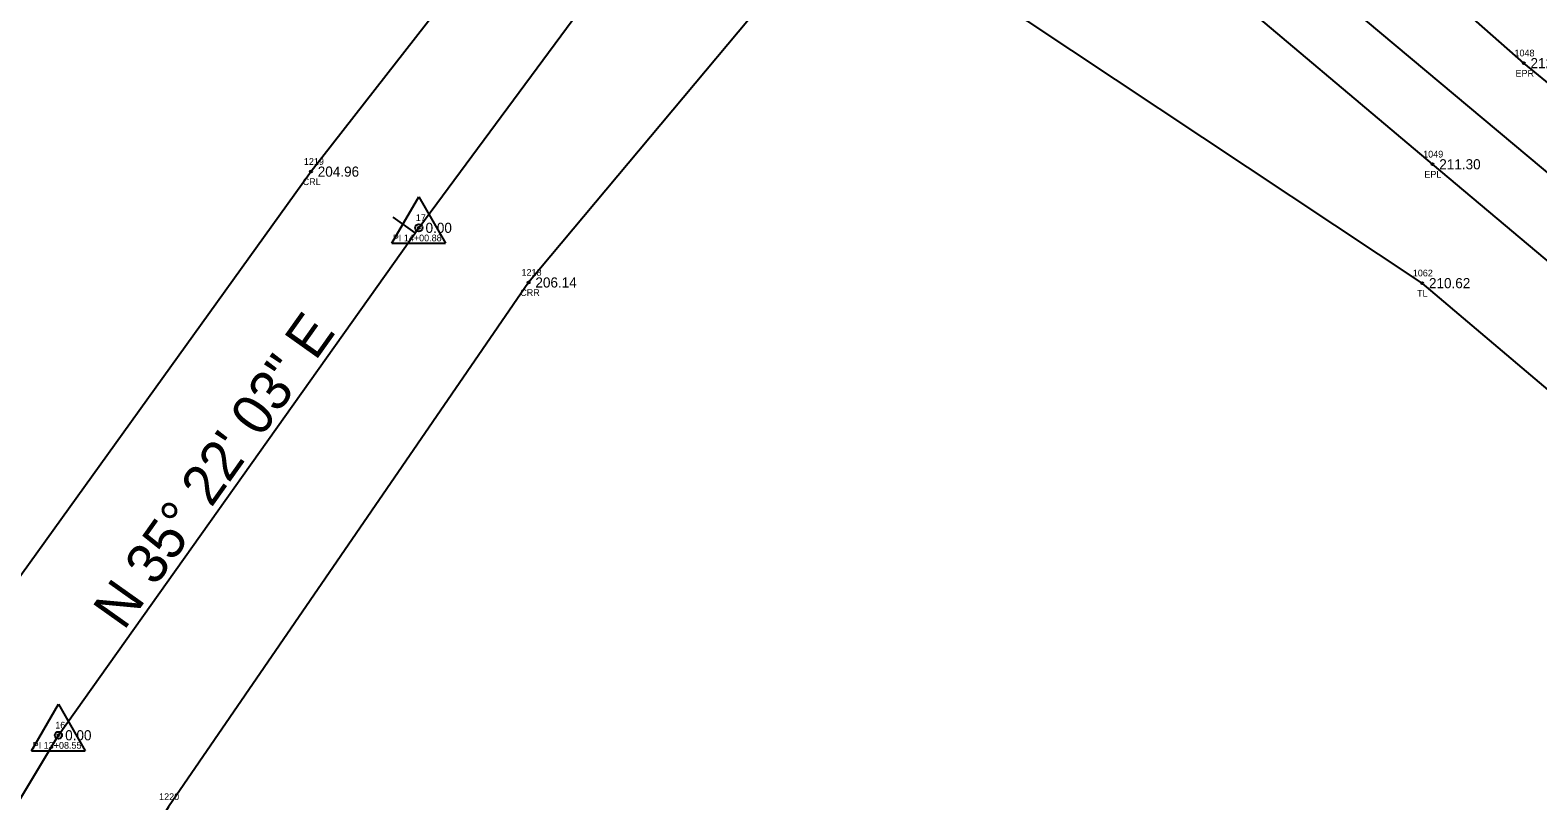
# Model space of a CAD drawing. Extents: x 2259948 to 2261336, y 1064647 to 1065986.
# Drawn here: x 2260676.5 to 2260900.1, y 1064908.1 to 1065022.5 of the extents above; entities that cross this region are included whole.
import ezdxf

# ---------------------------------------------------------------- set-up
doc = ezdxf.new("R2010")
doc.units = 0
for name, color, linetype in [('RD_EX_H2O', 7, 'Continuous'), ('RD_EX_H2O_txCode', 7, 'Continuous'), ('RD_EX_Road', 7, 'Continuous'), ('RD_EX_Road_txCode', 7, 'Continuous'), ('RD_EX_TX_H2O_ELEV', 7, 'Continuous'), ('RD_EX_TX_Road_ELEV', 7, 'Continuous'), ('RD_EX_TX_VEG_ELEV', 7, 'Continuous'), ('RD_EX_VEG', 7, 'Continuous'), ('RD_EX_VEG_txCode', 7, 'Continuous'), ('RD_HC_Cl', 7, 'Continuous'), ('RD_HC_Data', 7, 'Continuous'), ('RD_HC_Data_Tic', 7, 'Continuous'), ('RD_HC_Survey_ELEV', 7, 'Continuous'), ('RD_HC_txCode', 7, 'Continuous'), ('RD_SMD_Locator', 7, 'Continuous')]:
    doc.layers.add(name, color=color, linetype=linetype)

msp = doc.modelspace()

# ---------------------------------------------------------------- linework, layer by layer
at = {"layer": 'RD_EX_H2O'}
for points in [[(2260766.96, 1065089.79), (2260769.94, 1065084.22), (2260769.59, 1065075.21), (2260766.59, 1065063.56), (2260718.2, 1065001.51), (2260666.03, 1064928.94), (2260617.31, 1064851.47), (2260573.34, 1064761.94), (2260536.11, 1064718.88), (2260488.15, 1064682.39)], [(2260814.11, 1065053.05), (2260812.59, 1065051.01), (2260806.25, 1065051.8), (2260750.48, 1064985.06), (2260697.06, 1064907.27), (2260648.8, 1064826.07), (2260606.38, 1064743.85), (2260584.89, 1064714.82), (2260586.34, 1064702.25), (2260547.45, 1064661.75), (2260541.67, 1064664.24), (2260523.34, 1064649.3)]]:
    msp.add_lwpolyline(points, dxfattribs=at)
at = {"layer": 'RD_EX_Road'}
for points in [[(2261124.91, 1064827.37), (2261072.16, 1064871.6), (2261053.72, 1064886.47), (2261045.58, 1064893.1), (2260972.89, 1064954.76), (2260940.74, 1064982.39), (2260933.33, 1064988.76), (2260898.06, 1065017.6), (2260832.89, 1065075.07)], [(2261112.68, 1064810.86), (2261032.95, 1064877.72), (2260956.01, 1064942.53), (2260884.53, 1065002.6), (2260818.6, 1065058.26)]]:
    msp.add_lwpolyline(points, dxfattribs=at)
at = {"layer": 'RD_EX_VEG'}
msp.add_lwpolyline([(2261105.29, 1064796.67), (2260883, 1064984.96), (2260766.14, 1065062.68), (2260367.33, 1065416.28), (2260257.33, 1065527.76)], dxfattribs=at)
at = {"layer": 'RD_HC_Cl'}
for p, q in [((2261118.79, 1064819.11), (2260589.55, 1065263.13)), ((2260734.19, 1064993.17), (2260819.36, 1065108.41)), ((2260680.74, 1064917.88), (2260734.19, 1064993.17)), ((2260632.73, 1064838.31), (2260680.74, 1064917.88))]:
    msp.add_line(p, q, dxfattribs=at)
at = {"layer": 'RD_HC_Data'}
for p, q in [((2260730.21, 1064990.88), (2260734.19, 1064997.76)), ((2260734.19, 1064997.76), (2260738.16, 1064990.88)), ((2260730.21, 1064990.88), (2260738.16, 1064990.88)), ((2260676.77, 1064915.59), (2260680.74, 1064922.47)), ((2260680.74, 1064922.47), (2260684.71, 1064915.59)), ((2260676.77, 1064915.59), (2260684.71, 1064915.59))]:
    msp.add_line(p, q, dxfattribs=at)
for centre in [(2260734.19, 1064993.17), (2260680.74, 1064917.88)]:
    msp.add_circle(centre, 0.529, dxfattribs=at)
at = {"layer": 'RD_HC_Data_Tic'}
msp.add_line((2260733.67, 1064992.45), (2260730.41, 1064994.77), dxfattribs=at)
at = {"layer": 'RD_SMD_Locator'}
for centre in [(2260898.06, 1065017.6), (2260718.2, 1065001.51), (2260884.53, 1065002.6), (2260734.19, 1064993.17), (2260750.48, 1064985.06), (2260883, 1064984.96), (2260680.74, 1064917.88)]:
    msp.add_circle(centre, 0.15, dxfattribs=at)

# ---------------------------------------------------------------- texts
at = {"layer": 'RD_EX_H2O_txCode'}
for s, p in [('1219', (2260717.14, 1065002.51)), ('CRL', (2260716.97, 1064999.51)), ('1218', (2260749.42, 1064986.06)), ('CRR', (2260749.23, 1064983.06)), ('1220', (2260695.67, 1064908.27))]:
    msp.add_text(s, height=1, dxfattribs=at).set_placement(p)
at = {"layer": 'RD_EX_Road_txCode'}
for s, p in [('1048', (2260896.68, 1065018.6)), ('EPR', (2260896.84, 1065015.6)), ('1049', (2260883.14, 1065003.6)), ('EPL', (2260883.32, 1065000.6))]:
    msp.add_text(s, height=1, dxfattribs=at).set_placement(p)
at = {"layer": 'RD_EX_TX_H2O_ELEV'}
for s, p in [('204.96', (2260719.2, 1065000.76)), ('206.14', (2260751.48, 1064984.31))]:
    msp.add_text(s, height=1.5, dxfattribs=at).set_placement(p)
at = {"layer": 'RD_EX_TX_Road_ELEV'}
for s, p in [('212.25', (2260899.06, 1065016.85)), ('211.30', (2260885.53, 1065001.85))]:
    msp.add_text(s, height=1.5, dxfattribs=at).set_placement(p)
at = {"layer": 'RD_EX_TX_VEG_ELEV'}
msp.add_text('210.62', height=1.5, dxfattribs=at).set_placement((2260884, 1064984.21))
at = {"layer": 'RD_EX_VEG_txCode'}
for s, p in [('1062', (2260881.6, 1064985.96)), ('TL', (2260882.23, 1064982.96))]:
    msp.add_text(s, height=1, dxfattribs=at).set_placement(p)
at = {"layer": 'RD_HC_Data'}
msp.add_text('N 35%%d 22\' 03" E', height=6, rotation=54.6324, dxfattribs=at).set_placement((2260690.45, 1064933.29))
at = {"layer": 'RD_HC_Survey_ELEV'}
for p in [(2260735.19, 1064992.42), (2260681.74, 1064917.13)]:
    msp.add_text('0.00', height=1.5, dxfattribs=at).set_placement(p)
at = {"layer": 'RD_HC_txCode'}
for s, p in [('17', (2260733.74, 1064994.17)), ('PI 14+00.88', (2260730.33, 1064991.17)), ('16', (2260680.27, 1064918.88)), ('PI 13+08.55', (2260676.92, 1064915.88))]:
    msp.add_text(s, height=1, dxfattribs=at).set_placement(p)

doc.saveas('drawing.dxf')
